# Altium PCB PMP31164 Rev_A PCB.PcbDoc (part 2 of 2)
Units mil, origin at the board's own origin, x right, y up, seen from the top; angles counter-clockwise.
Board outline 4675 x 1875 mil, 2 copper layers (Top Layer, Bottom Layer), stack 62 mil thick; 52 components, 23 nets, 102 pads, 63 vias.
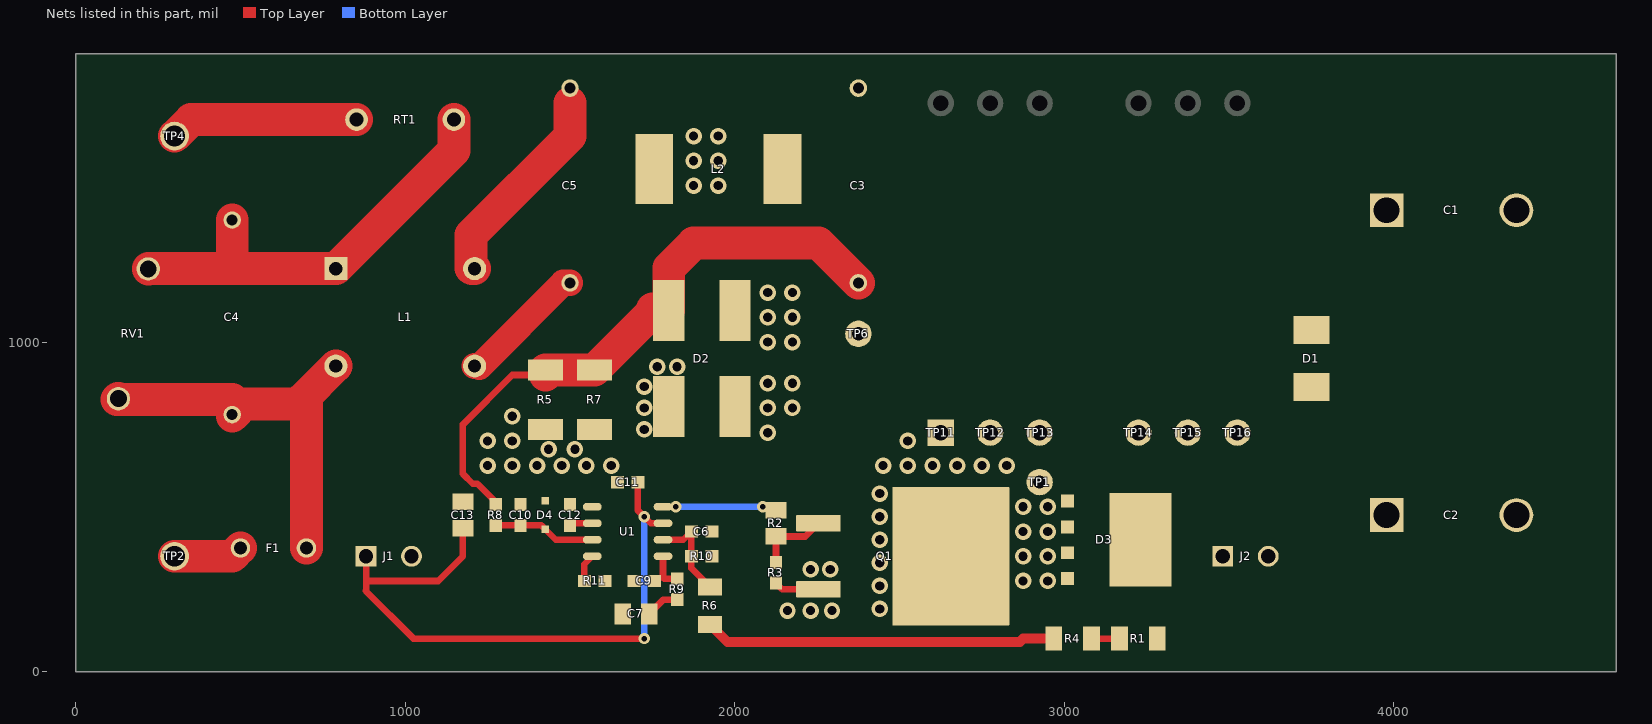
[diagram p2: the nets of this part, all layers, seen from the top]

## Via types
v1: diameter 50, hole 28, Top Layer to Bottom Layer, 59 vias
v2: diameter 34, hole 16, Top Layer to Bottom Layer, 4 vias

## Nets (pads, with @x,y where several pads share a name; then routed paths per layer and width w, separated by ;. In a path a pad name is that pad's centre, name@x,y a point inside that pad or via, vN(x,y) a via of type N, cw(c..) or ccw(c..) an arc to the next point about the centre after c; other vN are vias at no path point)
NetC1_1: C1.1 C2.1 D1.1 D3.5 J2.1 R1.2
NetC3_1: C3.1 D1.2 L2.2 TP6.1 TP14.1 TP15.1 TP16.1
NetC3_2: C3.2 D2.4 R5.1 R7.1 R8.2 | length 1864.5
  Top Layer w20: R8.2@1275,506.5 1275,513.93 1231.96,556.96 1218.93,570 1205,570 1175,600 1175,750 1325,900 R5.1@1425,900
  Top Layer w30: R5.1@1425,915.55 R5.1@1425,925
  Top Layer w100: R5.1@1425,900 R5.1@1425,915.55 ; R5.1@1434.45,915.55 R7.1@1575,915.55 1750,1090.55 1750,1100 1795.28,1100 D2.4@1799.61,1095.67 1799.61,1224.61 1875,1300 2254.72,1300 C3.2@2375,1179.72
NetC4_1: C4.1 F1.1 L1.2 RV1.2 | length 1246.5
  Top Layer w100: RV1.2@129.72,828.15 128.15,828.15 125,825 475,825 C4.1@475,779.72 475,775 512.01,812.01 700,812.01 ; F1.1@700,375 700,812.01 ; L1.2@789.37,927.36 687.01,825 700,812.01
NetC4_2: C4.2 L1.1 RT1.2 RV1.1 | length 1317.8
  Top Layer w100: RV1.1@220.28,1221.85 221.06,1222.64 475,1222.64 ; C4.2@475,1370.28 475,1222.64 ; RT1.2@1147.64,1675 1147.64,1580.91 L1.1@789.37,1222.64 475,1222.64
NetC5_1: C5.1 D2.2 L1.3 | length 395.9
  Top Layer w80: L1.3@1210.63,927.36 1222.64,927.36 1225,925 1479.72,1179.72 C5.1@1500,1179.72
  other v1: 2100,725 2100,800 2175,800 2100,875 2175,875
NetC5_2: C5.2 D2.3 L1.4 | length 635.9
  Top Layer w100: L1.4@1210.63,1222.64 1202.36,1222.64 1200,1225 1200,1325 1500,1625 1500,1725
  other v1: 1725,735 1725,800 1725,865 1765,925 1825,925
NetC6_1: C6.1 R6.1 R10.2 U1.6 | length 287.9
  Top Layer w20: U1.6@1782.28,400 1793.03,400 1843.5,400 C6.1@1868.5,425 R10.2@1868.5,350 1868.5,313.58 R6.1@1925,257.09
NetC7_1: C7.1 R9.1 | length 103
  Top Layer w20: C7.1@1740,175 1783.5,218.5 R9.1@1825,218.5
NetC9_1: C9.1 R9.2 U1.5 | length 109
  Top Layer w20: U1.5@1782.28,350 1782.28,285.24 1786.02,281.5 R9.2@1825,281.5
NetC10_1: C10.1 D4.1 R8.1 U1.3 | length 310.7
  Top Layer w20: R8.1@1275,443.5 C10.1@1350,443.5 1413.19,443.5 D4.1@1425,431.69 1456.69,400 1556.81,400 U1.3@1567.72,400
NetC11_1: C11.1 C13.1 J1.1 U1.7 | length 1970
  Top Layer w20: J1.1@881.1,350 881.1,275 ; C13.1@1175,435 1175,350 1100,275 881.1,275 ; C11.1@1706.5,575 1705,573.5 1705,490 v2(1725,470) 1745,450 U1.7@1782.28,450 ; v2(1725,100) 1025,100 880,245 881.1,246.1 881.1,275
  Bottom Layer w20: v2(1725,100) v2(1725,470)
NetC12_1: C12.1 U1.2 | length 70.4
  Top Layer w20: C12.1@1500,443.5 1506.5,450 U1.2@1567.72,450
NetD2_1: D2.1 L2.1
  other v1: 2100,1000 2175,1000 2100,1075 2175,1075 2100,1150 2175,1150 1875,1475 1950,1475 1875,1550 1950,1550 1875,1625 1950,1625
NetD3_3: D3.1 D3.2 D3.3 D3.4 Q1.2 TP1.1 TP11.1 TP12.1 TP13.1
  other v1: 2440,190 2440,260 2875,275 2950,275 2440,330 2875,350 2950,350 2440,400 2875,425 2950,425 2440,470 2875,500 2950,500 2440,540 2450,625 2525,625 2600,625 2675,625 2750,625 2825,625 2525,700
NetF1_2: F1.2 TP2.1 | length 210.4
  Top Layer w100: TP2.1@300,350 475,350 F1.2@500,375
NetQ1_1: Q1.1 R2.2 R3.2 | length 224
  Top Layer w20: R3.2@2125,331.5 R2.2@2125,410 2213.94,410 Q1.1@2253.94,450
NetR1_1: R1.1 R4.2 | length 85.8
  Top Layer w20: R4.2@3082.09,100 R1.1@3167.91,100
NetR2_1: R2.1 U1.8 | length 278.5
  Top Layer w20: R2.1@2115,500 R2.1@2125,490
  Bottom Layer w20: v2(1820.67,500) v2(2085,500)
NetR4_1: R4.1 R6.2 | length 1069
  Top Layer w30: R6.2@1925,142.91 1977.91,90 2865,90 2875,100 R4.1@2967.91,100
NetR11_2: R11.2 U1.4 | length 85
  Top Layer w20: R11.2@1543.5,275 1543.5,325.79 U1.4@1567.72,350
NetRT1_1: RT1.1 TP4.1 | length 573.1
  Top Layer w100: TP4.1@300,1625 350,1675 RT1.1@852.36,1675
PGND: C1.2 C2.2 C6.2 C7.2 C9.2 C10.2 C11.2 C12.2 C13.2 D4.2 J1.2 J2.2 Q1.3 R3.1 R5.2 R7.2 R10.1 R11.1 U1.1 | length 136.6
  Top Layer w20: R3.1@2125,268.5 2143.5,250 Q1.3@2253.94,250
  other v1: 2160,185 2230,185 2295,185 2230,310 2290,310 1250,625 1325,625 1400,625 1475,625 1550,625 1625,625 1435,675 1515,675 1250,700 1325,700 1325,775
pads on no net: TP17.1 TP18.1 TP19.1 TP110.1 TP111.1 TP112.1

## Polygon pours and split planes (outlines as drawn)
PGND on Top Layer "TOP_LAYER_PGND_P014" (solid, pour order 14): 2175,300 2225,350 2325,350 2325,150 2100,150 2096.46,153.54 2096.46,300
PGND on Top Layer "TOP_LAYER_PGND_P013" (solid, pour order 13): 1632.09,825 1650,807.09 1650,675 1675,650 1875,650 1925,600 2075,600 2075,125 1975,25 950,25 950,525 1250,825
NetC1_1 on Top Layer "TOP_LAYER_NETC1_1_P009" (solid, pour order 9): 3850,950 3800,900 3700,900 3700,650 3675,625 3150,625 3125,600 3125,250 3175,250 3250,175 3250,75 4200,75 4275,150 4275,1600 3800,1600 3750,1550 3750,1175 3850,1075
NetD3_3 on Top Layer "TOP_LAYER_NETD3_3_P008" (solid, pour order 8): 2400,650 2500,750 2600,850 3000,850 3050,800 3050,275 3000,225 2900,225 2825,150 2425,150 2400,175
NetC3_2 on Top Layer "TOP_LAYER_NETC3_2_P007" (solid, pour order 7): 1425,956.89 1431.89,956.89 1625,1150 1625,1300 1675,1350 1850,1350 1875,1325 1875,1050 1825,1000 1725,1000 1650,925 1650,875 1625,850 1375,850 1367.91,857.09 1367.91,932.48
NetC3_1 on Top Layer "TOP_LAYER_NETC3_1_P006" (solid, pour order 6): 3700,1000 3625,925 3625,725 3575,675 3175,675 3125,725 3125,825 3025,925 2625,925 2550,1000 2325,1000 2325,1075 2500,1075 2550,1125 2550,1225 2350,1425 2075,1425 2075,1800 2450,1800 2500,1750 2500,1650 2875,1275 3550,1275 3750,1075 3800,1075 3800,1000
NetD2_1 on Top Layer "TOP_LAYER_NETD2_1_P003" (solid, pour order 3): 1650,1800 2000,1800 2000,1425 1975,1400 1650,1400
NetC5_2 on Top Layer "TOP_LAYER_NETC5_2_P002" (solid, pour order 2): 1750,950 1850,950 1850,700 1700,700 1700,900
NetC5_1 on Top Layer "TOP_LAYER_NETC5_1_P001" (solid, pour order 1): 2250,925 2250,675 1925,675 1925,925
NetD2_1 on Top Layer "TOP_LAYER_NETD2_1_P000" (solid, pour order 0): 1950,1200 2200,1200 2250,1150 2250,975 1950,975
PGND on Bottom Layer "BOTTOM_LAYER_PGND_P012" (solid, pour order 12): 825,1850 4650,1850 4650,25 825,25
NetD3_3 on Bottom Layer "BOTTOM_LAYER_NETD3_3_P011" (solid, pour order 11): 2400,650 2500,750 2600,850 3000,850 3050,800 3050,275 3000,225 2900,225 2825,150 2425,150 2400,175
NetC5_1 on Bottom Layer "BOTTOM_LAYER_NETC5_1_P010" (solid, pour order 10): 2250,790 2130,670 1930,670 1925,675 1925,975 1875,1025 1600,1025 1450,1175 1450,1275 1475,1300 1796.06,1300 2000.39,1095.67 2000.39,974.61 2050,925 2250,925
NetC5_2 on Bottom Layer "BOTTOM_LAYER_NETC5_2_P005" (solid, pour order 5): 1325,1300 1400,1225 1400,1175 1600,975 1850,975 1875,950 1875,725 1850,700 1600,700 1150,1150 1150,1275 1175,1300
NetD2_1 on Bottom Layer "BOTTOM_LAYER_NETD2_1_P004" (solid, pour order 4): 2050,1000 2075,975 2250,975 2250,1150 2000,1400 2000,1675 1825,1675 1825,1325 2050,1100

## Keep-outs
Keep-Out Layer:
  text ".Layer_Name" at 577,-858.49 h60

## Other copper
Top Layer:
  text ".Layer_Name" at 577,-858.49 h60
Bottom Layer:
  text ".Layer_Name" at 577,-858.49 h60

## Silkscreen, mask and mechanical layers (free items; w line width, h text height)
Top Overlay:
  lines w10: 2525,950 2525,625 2775,625 ; 2525,1575 2525,1825 2850,1825 ; 3300,625 3625,625 3625,875 ; 3375,1825 3625,1825 3625,1500
  text "~" at 64.05,1519.61 h118.11 r338.2
  text "L3" at 3163.19,1286.81 h60 r90
  text "~" at 64.05,244.61 h118.11 r338.2
  text "15V" at 770,110 h60
  text "GND" at 985,110 h60
  text "Vout" at 3385,110 h60
  text "GND" at 3635,110 h60
  text "'.PRJ_Number'.PCB_Rev-" at 140,80 h108.27
  text ".Layer_Name" at 577,-858.49 h60
Bottom Overlay:
  text ".Layer_Name" at 577,-858.49 h60
Top Paste:
  text ".Layer_Name" at 577,-858.49 h60
Bottom Paste:
  text ".Layer_Name" at 577,-858.49 h60
Top Solder:
  text ".Layer_Name" at 577,-858.49 h60
  text ".Layer_Name" at 577,-858.49 h60
Bottom Solder:
  text ".Layer_Name" at 577,-858.49 h60
Drill Guide:
  text ".Layer_Name" at 577,-858.49 h60
M1 Board Outline:
  the board outline again, w10
  text ".Layer_Name" at 577,-858.49 h60
M2 Board Dimensions:
  rectangle: 0,-275 125,-150
  rectangle: 125,-400 500,-275
  lines w7: 0,-275 1000,-275 ; 125,-400 125,-150 ; 250,-400 250,-150 ; 500,-400 500,-150 ; 750,-400 750,-150 ; 0,-400 1000,-400 1000,-150 0,-150 0,-400
  text ".Layer_Name" at 577,-858.49 h60
M3 3D STEP Top:
  text ".Layer_Name" at 577,-858.49 h60
M4 3D STEP Bottom:
  text ".Layer_Name" at 577,-858.49 h60
M5 Assembly Top:
  lines w10: -292,-930.17 6308,-930.17 ; -292,-726.83 6310,-726.83 ; -292,-523.5 -292,-1133.5 3713,-1133.5 6310,-1133.5 6310,-523.5 -291.5,-523.5 -291.5,-1133.5 1284,-1133.5 ; 2173,-1133.5 2173,-523.5 ; 3440,-726.83 3440,-523.5 ; 4280,-726.83 4280,-523.5 ; 4902,-1140 4902,-937.17 ; 2525,625 2525,1825 3625,1825 3625,625 2525,625
  text "L3" at 3063.19,1086.81 h60 r90
  text "COMPONENTS MARKED 'DNP' SHOULD NOT BE POPULATED." at 1153.5,-318.5 h60
  text "ASSEMBLY VARIANT:" at 1153,-434 h60
  text ".VariantName" at 2189,-434 h60
  text "PCB VIEWED FROM TOP SIDE" at -228.5,-655.67 h60
  text "BOARD #:" at 2248,-655.67 h60
  text ".PRJ_Number" at 2793.5,-655.67 h60
  text "REV:" at 3638,-655.67 h60
  text ".PCB_Rev" at 3929.5,-655.67 h60
  text "SVN REV:" at 4476,-655.67 h60
  text ".VersionControl_RevNumber" at 4982,-655.67 h60
  text "TID #:" at 2248,-859 h60
  text ".TID" at 2793.5,-859 h60
  text "PLOT NAME =" at -228.5,-1064.34 h60
  text ".plot_File_Name" at 577,-1064.34 h60
  text "GENERATED    :" at 2250,-1064.34 h60
  text ".Print_Date" at 3119.5,-1064.34 h60
  text ".Print_Time" at 3848.5,-1064.34 h60
  text "TEXAS INSTRUMENTS" at 5113,-1064.34 h60
M6 Assembly Bottom:
  lines w10: -292.5,-727.33 6309.5,-727.33 ; -290.5,-930.67 6309.5,-930.67 ; 1115.5,-1140.5 1115.5,-937.67 ; 1737.5,-727.33 1737.5,-524 ; 2577.5,-727.33 2577.5,-524 ; 3844.5,-1134 3844.5,-524 ; 4733.5,-1134 6309,-1134 6309,-524 -292.5,-524 -292.5,-1134 2304.5,-1134 6309.5,-1134 6309.5,-524
  text "COMPONENTS MARKED 'DNP' SHOULD NOT BE POPULATED." at 6102,-318 h60
  text ".VariantName" at 5058,-434 h60
  text "ASSEMBLY VARIANT:" at 6097,-434 h60
  text ".VersionControl_RevNumber" at 1035.5,-656.17 h60
  text "SVN REV:" at 1541.5,-656.17 h60
  text ".PCB_Rev" at 2088,-656.17 h60
  text "REV:" at 2379.5,-656.17 h60
  text ".PRJ_Number" at 3224,-656.17 h60
  text "BOARD #:" at 3769.5,-656.17 h60
  text "PCB VIEWED FROM BOTTOM SIDE" at 6246,-656.17 h60
  text ".TID" at 3224,-859.5 h60
  text "TID #:" at 3769.5,-859.5 h60
  text "TEXAS INSTRUMENTS" at 904.5,-1064.84 h60
  text ".Print_Time" at 2169,-1064.84 h60
  text ".Print_Date" at 2898,-1064.84 h60
  text "GENERATED    :" at 3767.5,-1064.84 h60
  text ".plot_File_Name" at 5440.5,-1064.84 h60
  text "PLOT NAME =" at 6246,-1064.84 h60
M9 Title Sheet:
  drawing of 57 lines, arcs and shapes, not listed
  text "1" at 739.84,8036.5 h70
  text "2" at 3235.5,8036.5 h70
  text "3" at 5724.84,8036.5 h70
  text "4" at 8231.51,8036.5 h70
  text "5" at 10730.5,8036.5 h70
  text "6" at 13235.5,8036.5 h70
  text "A" at -416.5,6893.5 h70
  text "A" at 14383.5,6893.5 h70
  text "B" at -416.5,4513.5 h70
  text "B" at 14383.5,4513.5 h70
  text "C" at -416.5,2138.5 h70
  text "C" at 14383.5,2138.5 h70
  text "PROJECT TITLE:" at 11343.5,277.5 h45
  text ".PRJ_Title" at 11393.5,144.17 h70
  text "DESIGNED FOR:" at 11343.5,-23.5 h45
  text ".PRJ_Customer" at 11393.5,-163.5 h70
  text "D" at -416.5,-231.5 h70
  text "D" at 14383.5,-231.5 h70
  text "FILE NAME:" at 11343.5,-323.5 h45
  text ".PCB_File_Name_No_Path" at 11393.5,-443.5 h70
  text "Texas Instruments (TI) and/or its licensors do not warrant the accuracy or completeness of this specification" at 6374,-605.34 h45
  text "ENGINEER:" at 11343.5,-613.5 h45
  text "LAYOUT BY:" at 12848.5,-613.5 h45
  text "or any information contained therein. TI and/or its licensors do not warrant that this design will meet" at 6329.01,-718 h45
  text ".PRJ_Engineer" at 11393.5,-768.49 h70
  text ".PCB_Layout" at 12899,-768.49 h70
  text "the specifications, will be suitable for your application or fit for any particular purpose, or will operate in" at 6329.01,-830.67 h45
  text ".Layer_Name" at 577,-858.49 h60
  text "ALTIUM DESIGNER VERSION:" at 12848.5,-923.5 h45
  text "an implementation. TI and/or its licensors do not warrant that the design is production worthy. You should" at 6329.01,-943.33 h45
  text "completely validate and test your design implementation to confirm the system functionality for your application." at 6374,-1056 h45
  text ".print_Scale" at 11393.5,-1056.83 h70
  text ".Application_BuildNumber" at 12899,-1056.83 h70
  text "1" at 739.84,-1263.5 h70
  text "2" at 3235.5,-1263.5 h70
  text "3" at 5724.84,-1263.5 h70
  text "4" at 8231.51,-1263.5 h70
  text "5" at 10730.5,-1263.5 h70
  text "6" at 13235.5,-1263.5 h70
M10 Fab Notes:
  drawing of 189 lines, arcs and shapes, not listed
  text "DESIGN INFORMATION" at 12382.02,6356.17 h60
  text "MIN. TRACK WIDTH:" at 11737.46,6224.05 h60
  text "8" at 12833.7,6224.05 h60
  text "MIL" at 12988.46,6224.05 h60
  text "MIN. CLEARANCE:" at 11737.46,6099.92 h60
  text "0.2" at 12773.7,6099.93 h60
  text "mm" at 12988.46,6099.92 h60
  text "MIN. VIA PAD SIZE:" at 11737.46,5975.8 h60
  text "24" at 12803.71,5975.8 h60
  text "MIL" at 12988.46,5975.8 h60
  text "0.05mm (2MIL)" at 12432.46,5845.9 h60
  text "MINIMUM ANNULAR RING" at 11408.23,5837.67 h60
  text "EXTERNAL" at 13140.46,5837.67 h60
  text "PER" at 11608.23,5727.55 h60
  text "IPC-D-275 CLASS 2 LEVEL C" at 11828.23,5727.54 h60
  text "MIL, HOLES" at 13316.46,5627.07 h60
  text "+/-" at 12924,5618.48 h60
  text "+/-" at 13778,5618.48 h60
  text "REGISTRATION TOLERANCES:" at 11408.23,5617.42 h60
  text "METAL" at 12608,5617.42 h60
  text "5" at 13184.2,5617.42 h60
  text "3" at 14017.2,5617.42 h60
  text "MIL" at 14133.46,5617.42 h60
  text "HOLE SIZE TOLERANCE (UNLESS OTHERWISE SPECIFIED):" at 11408.23,5519.1 h60
  text "+/-" at 13778,5516.23 h60
  text "3" at 14017.2,5515.17 h60
  text "MIL" at 14133.46,5515.17 h60
  text "MATERIAL:" at 11333.46,5377.52 h60
  text "FR-4 High Tg" at 12319.9,5249 h60
  text "X" at 12175.46,5241.01 h60
  text "FR-408" at 11754.46,5236.49 h60
  text "OTHER" at 13242.46,5236.49 h60
  text "62 MIL (1.6mm) +/-10%" at 12074.56,5093.46 h60
  text "X" at 11954.46,5091.01 h60
  text "THICKNESS:" at 11408.23,5085.24 h60
  text "OTHER" at 13359.46,5085.24 h60
  text "TOLERANCE:" at 11408.23,4946.92 h60
  text "X" at 12256.46,4946.92 h60
  text "ANSI IPC-6012 TYPE 3 CLASS 2" at 12434.48,4946.92 h60
  text "OTHER +/-" at 12434.46,4802.73 h60
  text "BOW & TWIST:" at 11408.23,4657.54 h60
  text "X" at 12256.46,4657.54 h60
  text "ANSI IPC-6012 TYPE 3 CLASS 2" at 12434.48,4657.54 h60
  text "OTHER +/-" at 12434.46,4510.85 h60
  text "DRILLING:" at 11333.46,4380.23 h60
  text "NC_DRILL FILES" at 13094.46,4275.04 h60
  text "REFERENCE:" at 11408.23,4271.1 h60
  text "X" at 12065.46,4271.01 h60
  text "AS SHOWN" at 12243.46,4271.1 h60
  text "X" at 12966.46,4271.1 h60
  text "OTHER" at 13392.46,4128.85 h60
  text "PTH COPPER THICKNESS:" at 11407.91,4125.32 h60
  text "X" at 12547.14,4125.32 h60
  text "20-30 um" at 12675.14,4125.32 h60
  text "BOARD FINISH:" at 11333.46,3977.73 h60
  text "SILKSCREEN:" at 11488.68,3867.6 h60
  text "X" at 12446.46,3867.6 h60
  text "TOP" at 12563.46,3867.6 h60
  text "X" at 12956.46,3867.6 h60
  text "BOTTOM" at 13074.46,3867.6 h60
  text "SILKSCREEN COLOR:" at 11488.68,3712.41 h60
  text "X" at 12445.46,3712.41 h60
  text "WHITE" at 12563.46,3712.41 h60
  text "OTHER" at 13074.46,3712.41 h60
  text "X" at 12576.46,3568.96 h60
  text "GREEN" at 12694.46,3568.96 h60
  text "OTHER" at 13312.46,3568.96 h60
  text "SOLDER RESIST COLOR:" at 11488.68,3562.1 h60
  text "X" at 12576.46,3414.71 h60
  text "MATTE" at 12694.46,3414.71 h60
  text "SEMI-GLOSS" at 13312,3414.07 h60
  text "IMMERSION GOLD (ENIG)" at 12394.46,3241.94 h60
  text "ENEPIG" at 13732,3234.72 h60
  text "SURFACE FINISH:" at 11333.46,3233.72 h60
  text "X" at 12216.46,3233.72 h60
  text "IMM. TIN/SILVER OR EQUIV" at 11663,3096.4 h60
  text "OTHER" at 13094.46,3092.47 h60
  text "ARRAY/PANEL:" at 11333.46,2937.09 h60
  text "CUT AND TRIM PER M1 BOARD OUTLINE" at 12394.46,2928.87 h60
  text "N.C. ROUTE" at 12394.46,2792.9 h60
  text "X" at 13082.46,2792.9 h60
  text "V. SCORE" at 13260.46,2792.9 h60
  text "CERTIFICATION:" at 11333.46,2663.77 h60
  text "MATERIALS AND WORKMANSHIP FOR ALL PCBS" at 12058.46,2663.77 h60
  text "TO MEET OR EXCEED THE REQUIREMENTS OF:" at 12058.46,2569.71 h60
  text "X" at 11695.97,2441.08 h60
  text "ANSI IPC-A-600F CLASS ->" at 11823.96,2441.08 h60
  text "X" at 13471.97,2441.08 h60
  text "2" at 13581.96,2441.08 h60
  text "1" at 13266.96,2439.58 h60
  text "3" at 13935.96,2439.58 h60
  text "X" at 12507.97,2293.39 h60
  text "RoHS" at 12635.96,2293.39 h60
  text "OTHER" at 13280.36,2293.39 h60
  text "PER ORDER" at 13677.42,2293.39 h60
  text "ALL BOARDS MUST MEET OR EXCEED UL94-V0 REQUIREMENTS." at 11361,2139.57 h60
  text "PCB MUST BEAR THE UL94V-0 UL REGISTERED MATERIAL ID NUMBER" at 11361,2023.5 h60
  text "ADDITIONAL REQUIREMENTS:" at 11333.46,1854.08 h60
  text "MICROSECTION:" at 11408.23,1746.95 h60
  text "YES" at 12313.96,1746.95 h60
  text "REQUIRED" at 13175.46,1602.62 h60
  text "BARE BOARD ELEC. TEST:" at 11408.23,1599.76 h60
  text "NONE" at 12713.96,1599.76 h60
  text "X" at 13057.46,1599.76 h60
  text "PER ORDER" at 13767.46,1599.76 h60
  text "XX MIL VIAS REQUIRE NON-CONDUCTIVE FILL AND PLANARIZE" at 11576.38,1394.82 h59
  text "XX MIL VIAS REQUIRE CONDUCTIVE FILL AND PLANARIZE" at 11584.38,1290.84 h60
  text "OUTER XX MIL TRACES REQUIRE 50 OHM SINGLE-ENDED IMPEDANCE" at 11583.39,1127.46 h58
  text "LAYER 2 & 3 (INNER LAYERS) XX MIL WIDE, XX MIL SPACE / TRACES REQUIRE 100 OHM DIFFERENTIAL IMPEDANCE" at 11575.39,891.74 h60
  text ".Layer_Name" at 577,-858.49 h60
M11 Gerber Information:
  lines w10: -292,-930.17 6308,-930.17 ; -292,-726.83 6310,-726.83 ; -292,-523.5 -292,-1133.5 3713,-1133.5 6310,-1133.5 6310,-523.5 -291.5,-523.5 -291.5,-1133.5 1284,-1133.5 ; 2173,-1133.5 2173,-523.5 ; 3440,-726.83 3440,-523.5 ; 4280,-726.83 4280,-523.5 ; 4902,-1140 4902,-937.17
  text "ALL ARTWORK VIEWED FROM TOP SIDE" at -228.5,-655.67 h60
  text "BOARD #:" at 2248,-655.67 h60
  text ".PRJ_Number" at 2793.5,-655.67 h60
  text "REV:" at 3638,-655.67 h60
  text ".PCB_Rev" at 3929.5,-655.67 h60
  text "SVN REV:" at 4476,-655.67 h60
  text ".VersionControl_RevNumber" at 4982,-655.67 h60
  text "LAYER NAME =" at -228.5,-858.49 h60
  text "TID #:" at 2248,-859 h60
  text ".TID" at 2793.5,-859 h60
  text "PLOT NAME =" at -228.5,-1064.34 h60
  text ".plot_File_Name" at 577,-1064.34 h60
  text "GENERATED    :" at 2250,-1064.34 h60
  text ".Print_Date" at 3119.5,-1064.34 h60
  text ".Print_Time" at 3848.5,-1064.34 h60
  text "TEXAS INSTRUMENTS" at 5113,-1064.34 h60
M12 Stackup:
  drawing of 191 lines, arcs and shapes, not listed
  text "Layer" at 9807.84,7852.5 h60
  text "Name" at 10217.76,7852.5 h60
  text "Material" at 11147.5,7852.5 h60
  text "Thickness" at 12007.27,7852.5 h60
  text "Constant" at 12657.1,7852.5 h60
  text "Board Layer Stack" at 13226.96,7852.5 h60
  text "Top Overlay" at 10217.76,7732.5 h60
  text "Top Solder" at 10217.76,7612.5 h60
  text "Solder Resist" at 11147.5,7612.5 h60
  text "0.40mil" at 12007.27,7612.5 h60
  text "3.5" at 12657.1,7612.5 h60
  text "1" at 9807.84,7492.5 h60
  text "Top Layer" at 10217.76,7492.5 h60
  text "1.40mil" at 12007.27,7492.5 h60
  text "Dielectric1" at 10217.76,7372.5 h60
  text "FR-4" at 11147.5,7372.5 h60
  text "59.20mil" at 12007.27,7372.5 h60
  text "4.8" at 12657.1,7372.5 h60
  text "2" at 9807.84,7252.5 h60
  text "Bottom Layer" at 10217.76,7252.5 h60
  text "1.40mil" at 12007.27,7252.5 h60
  text "Bottom Solder" at 10217.76,7132.5 h60
  text "Solder Resist" at 11147.5,7132.5 h60
  text "0.40mil" at 12007.27,7132.5 h60
  text "3.5" at 12657.1,7132.5 h60
  text "Bottom Overlay" at 10217.76,7012.5 h60
  text ".Layer_Name" at 577,-858.49 h60
M13 Component Bodies Top:
  text ".Layer_Name" at 577,-858.49 h60
M14 Component Bodies Bottom:
  text ".Layer_Name" at 577,-858.49 h60
M15 Courtyards Top:
  text ".Layer_Name" at 577,-858.49 h60
M16 Courtyards Bottom:
  text ".Layer_Name" at 577,-858.49 h60
Drill Drawing:
  circle w10: c5363.82,3260.02 r27.67
  circle w10: c5363.82,2513.02 r16.6
  circle w10: c5363.82,2513.02 r27.67
  lines w10: 5336.16,2125.68 5349.99,2125.68 5349.99,2111.85 5377.66,2111.85 5377.66,2125.68 5391.49,2125.68 5391.49,2153.35 5377.66,2153.35 5377.66,2167.18 5349.99,2167.18 5349.99,2153.35 5336.16,2153.35 5336.16,2125.68 ; 5336.16,2236.35 5363.82,2250.18 5391.49,2236.35 5377.66,2264.02 5391.49,2291.68 5363.82,2277.85 5336.16,2291.68 5349.99,2264.02 5336.16,2236.35 ; 5336.16,2388.52 5363.82,2360.85 5391.49,2388.52 5363.82,2416.18 5336.16,2388.52 ; 5336.16,2609.85 5391.49,2609.85 5391.49,2665.18 5336.16,2665.18 5336.16,2609.85 ; 5336.16,2789.68 5391.49,2789.68 5363.82,2734.35 5336.16,2789.68 ; 5336.16,2872.68 5349.99,2872.68 5363.82,2858.85 5377.66,2872.68 5391.49,2872.68 5377.66,2886.52 5391.49,2900.35 5377.66,2900.35 5363.82,2914.18 5349.99,2900.35 5336.16,2900.35 5349.99,2886.52 5336.16,2872.68 ; 5336.16,2983.35 5336.16,2997.18 5349.99,3011.02 5336.16,3024.85 5336.16,3038.68 5349.99,3038.68 5363.82,3024.85 5377.66,3038.68 5391.49,3038.68 5391.49,3024.85 5377.66,3011.02 5391.49,2997.18 5391.49,2983.35 5377.66,2983.35 5363.82,2997.18 5349.99,2983.35 5336.16,2983.35 ; 5336.16,3107.85 5391.49,3107.85 5391.49,3163.18 5336.16,3163.18 5336.16,3107.85 ; 5347.23,2620.92 5380.43,2620.92 5380.43,2654.12 5347.23,2654.12 5347.23,2620.92
  lines w12: 5286,2074.5 8518.19,2074.5 ; 5286,3319.5 8518.19,3319.5 ; 5624.01,1950 5624.01,3444 ; 5956.17,1950 5956.17,3444 ; 6592.65,1950 6592.65,3444 ; 6851.85,1950 6851.85,3444 ; 7227.09,1950 7227.09,3444 ; 7951.64,1950 7951.64,3444 ; 5286,1950 8518.19,1950 8518.19,3444 5286,3444 5286,1950
  text "Symbol" at 5360.7,3356.85 h72
  text "Quantity" at 5661.36,3356.85 h72
  text "Finished Hole Size" at 5993.52,3356.85 h72
  text "Plated" at 6630,3356.85 h72
  text "Hole Type" at 6889.2,3356.85 h72
  text "Drill Layer Pair" at 7264.44,3356.85 h72
  text "Hole Tolerance" at 7988.99,3356.85 h72
  text "4" at 5661.36,3232.35 h60
  text "16.00mil (0.406mm)" at 5993.52,3232.35 h60
  text "PTH" at 6630,3232.35 h60
  text "Round" at 6889.2,3232.35 h60
  text "Top Layer - Bottom Layer" at 7264.44,3232.35 h60
  text "59" at 5661.36,3107.85 h60
  text "28.00mil (0.711mm)" at 5993.52,3107.85 h60
  text "PTH" at 6630,3107.85 h60
  text "Round" at 6889.2,3107.85 h60
  text "Top Layer - Bottom Layer" at 7264.44,3107.85 h60
  text "6" at 5661.36,2983.35 h60
  text "33.47mil (0.850mm)" at 5993.52,2983.35 h60
  text "PTH" at 6630,2983.35 h60
  text "Round" at 6889.2,2983.35 h60
  text "Top Layer - Bottom Layer" at 7264.44,2983.35 h60
  text "2" at 5661.36,2858.85 h60
  text "39.37mil (1.000mm)" at 5993.52,2858.85 h60
  text "PTH" at 6630,2858.85 h60
  text "Round" at 6889.2,2858.85 h60
  text "Top Layer - Bottom Layer" at 7264.44,2858.85 h60
  text "6" at 5661.36,2734.35 h60
  text "40.00mil (1.016mm)" at 5993.52,2734.35 h60
  text "PTH" at 6630,2734.35 h60
  text "Round" at 6889.2,2734.35 h60
  text "Top Layer - Bottom Layer" at 7264.44,2734.35 h60
  text "6" at 5661.36,2609.85 h60
  text "43.31mil (1.100mm)" at 5993.52,2609.85 h60
  text "PTH" at 6630,2609.85 h60
  text "Round" at 6889.2,2609.85 h60
  text "Top Layer - Bottom Layer" at 7264.44,2609.85 h60
  text "12" at 5661.36,2485.35 h60
  text "47.24mil (1.200mm)" at 5993.52,2485.35 h60
  text "PTH" at 6630,2485.35 h60
  text "Round" at 6889.2,2485.35 h60
  text "Top Layer - Bottom Layer" at 7264.44,2485.35 h60
  text "2" at 5661.36,2360.85 h60
  text "51.18mil (1.300mm)" at 5993.52,2360.85 h60
  text "PTH" at 6630,2360.85 h60
  text "Round" at 6889.2,2360.85 h60
  text "Top Layer - Bottom Layer" at 7264.44,2360.85 h60
  text "2" at 5661.36,2236.35 h60
  text "63.00mil (1.600mm)" at 5993.52,2236.35 h60
  text "PTH" at 6630,2236.35 h60
  text "Round" at 6889.2,2236.35 h60
  text "Top Layer - Bottom Layer" at 7264.44,2236.35 h60
  text "4" at 5661.36,2111.85 h60
  text "78.74mil (2.000mm)" at 5993.52,2111.85 h60
  text "PTH" at 6630,2111.85 h60
  text "Round" at 6889.2,2111.85 h60
  text "Top Layer - Bottom Layer" at 7264.44,2111.85 h60
  text "103 Total" at 5661.36,1987.35 h60
  text ".Layer_Name" at 577,-858.49 h60
M17 Embedded Cavity:
  text ".Layer_Name" at 577,-858.49 h60
M18 Embedded Assembly:
  text ".Layer_Name" at 577,-858.49 h60
M19 Embedded Keepout:
  text ".Layer_Name" at 577,-858.49 h60

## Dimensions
0,0 to 4675,0 on M2 Board Dimensions
0,-400 to 1000,-400 on M2 Board Dimensions
0,0 to 0,1875 on M2 Board Dimensions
